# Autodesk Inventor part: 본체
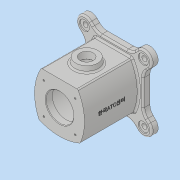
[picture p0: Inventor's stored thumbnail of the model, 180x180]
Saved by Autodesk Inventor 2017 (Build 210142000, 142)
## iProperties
Part Number: 본체
Material: 일반
Document SubType Name: Modeling
Designer: Administrator
Density: 1 g/cm^3
Appearance: 기본값
Author: Administrator
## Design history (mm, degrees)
sketch "스케치1"
  geometry: L1 (-53, 53)-(53, 53); L2 (53, 53)-(53, -53); L3 (53, -53)-(-53, -53); L4 (-53, -53)-(-53, 53); L5 (-53, 53)-(53, -53); L6 (53, 53)-(-53, -53); 1 further point
  constraints: 12 end point, 2 midpoint, 2 parallel, 1 horizontal, 1 perpendicular
  dimensions: "d0" = 106 distance of L1.end L2.end; "d1" = 106 distance of L1.start L1.end
extrude "돌출1" new body sketch "스케치1" distance "d5" = 12; taper "d6" = 0 deg
sketch "스케치2"
  geometry: L1 (53, 53)-(-53, 53) reference; L2 (0, 53)-(0, 0); L3 (-53.033, 53.033)-(0, 0); L4 (-63.64, 42.426)-(-44.143, 22.93); L5 (-42.426, 63.64)-(-22.93, 44.143); L6 (-44.143, 22.93)-(-22.93, 44.143); A1 r 15 centre (-53.033, 53.033) between (-42.426, 63.64) and (-63.64, 42.426)
  constraints: 10 end point, 2 parallel, 2 point on circle, 2 tangent, 1 centre point, 1 coincident, 1 midpoint, 1 vertical
  dimensions: "d87" = 30 diameter of A1; "d88" = 45 deg angle of L2 L3; "d89" = 75 distance of L3.start L3.end; "d90" = 21.2132 horizontal distance of L4.end L5.end; "d91" = 19.49686 horizontal distance of L5.start L5.end
extrude "돌출2" join sketch "스케치2" distance "d10" = 12; taper "d11" = 0 deg
sketch "스케치3"
  geometry: L1 (-45, 45)-(-32.942, 45); L2 (45, 45)-(45, -45); L3 (45, -45)-(-45, -45); L4 (-45, -45)-(-45, 45); L5 (-45, 45)-(45, -45); L6 (45, 45)-(-45, -45); L7 (-45, 0)-(45, 0); L8 (32.942, 45)-(45, 45); L9 (-32.942, 45)-(32.942, 45); A1 r 90 centre (0, 45) between (-45, -32.942) and (-37.029, -37.029); A2 r 90 centre (45, 0) between (-32.942, 45) and (-37.029, -37.029); A3 r 90 centre (-45, 0) between (32.942, -45) and (37.029, -37.029); A4 r 90 centre (0, 45) between (-37.029, -37.029) and (37.029, -37.029); A5 r 90 centre (45, 0) between (-37.029, -37.029) and (-32.942, -45); A6 r 90 centre (-45, 0) between (37.029, -37.029) and (32.942, 45); A7 r 90 centre (0, 45) between (37.029, -37.029) and (45, -32.942); 4 further points
  constraints: 18 end point, 18 point on circle, 7 centre point, 5 midpoint, 5 point on line, 5 tangent, 4 horizontal, 4 parallel, 3 perpendicular, 2 horizontal alignment, 1 vertical alignment
  dimensions: "d15" = 90 distance of L2.start L2.end; "d16" = 90 distance of L1.start L2.start; "d17" = 90 radius of A1; "d18" = 90 radius of A2; "d19" = 90 radius of A3; "d20" = 90 distance of L7.start L7.end
extrude "돌출3" join sketch "스케치3" distance "d21" = 98; taper "d22" = 0 deg
node "작업 평면1"
sketch "스케치4"
  geometry: L1 (31.787, 0)-(-31.787, 0) reference; C1 r 20 at (0, 61); 1 further point
  constraints: 1 centre point, 1 vertical alignment
  dimensions: "d24" = 40 diameter of C1; "d25" = 61 distance from line of L1 C1.centre
extrude "돌출4" join sketch "스케치4" stored distance "d26" = 98; taper "d27" = 10 deg
sketch "스케치5"
  geometry: C1 r 25 at (0, 0); 1 further point
  constraints: 1 centre point, 1 coincident
  dimensions: "d28" = 50 diameter of C1
extrude "돌출5" cut sketch "스케치5" distance "d29" = 12; taper "d30" = 0 deg
sketch "스케치6"
  geometry: C1 r 37 at (0, 0); 1 further point
  constraints: 1 centre point, 1 coincident
  dimensions: "d31" = 74 diameter of C1
extrude "돌출6" cut sketch "스케치6" distance "d32" = 86; taper "d33" = 0 deg
sketch "스케치7"
  geometry: C1 r 25 at (0, 0); 1 further point
  constraints: 1 centre point, 1 coincident
  dimensions: "d34" = 50 diameter of C1
extrude "돌출7" cut sketch "스케치7" stored distance "d35" = 86; taper "d36" = 0 deg
sketch "스케치8"
  geometry: C1 r 20 at (0, 0) reference; C2 r 12 at (0, 0); 1 further point
  constraints: 1 centre point, 1 coincident
  dimensions: "d37" = 24 diameter of C2
extrude "돌출8" cut sketch "스케치8" distance "d38" = 13; taper "d39" = 0 deg
sketch "스케치9"
  geometry: C1 r 12 at (0, 0) reference; C2 r 15 at (0, 0); 1 further point
  constraints: 1 centre point, 1 coincident
  dimensions: "d40" = 30 diameter of C2
extrude "돌출9" cut sketch "스케치9" stored distance "d41" = 13; taper "d42" = 0 deg
fillet "모깎기1" dims "d43" = 20
sketch "스케치10"
  geometry: L1 (0, 40)-(0, 0); L2 (0, 0)-(-28.284, 28.284); A1 r 40 centre (0, 0) between (0, 40) and (-28.284, 28.284); 2 further points
  constraints: 4 end point, 2 coincident, 2 point on circle, 1 centre point, 1 vertical
  dimensions: "d44" = 80 diameter of A1; "d45" = 45 deg angle of L1 L2
hole "구멍1" sketch "스케치10" at (-28.284, 28.284) diameter "d46" = 3.242; stored, may be unused: countersink angle "d50" = 90 deg, drill point angle "d52" = 118 deg; dims "d47" = 9, "d48" = 4, "d49" = 2, "d51" = 11
node "작업 평면2"
sketch "스케치12"
  geometry: L1 (31.787, 0)-(-31.787, 0) reference; L2 (55, 81)-(55, 41) reference; 4 further points
  constraints: 1 other
  dimensions: "d64" = 61 distance from line of L1 point (0, 61); "d65" = 55 distance from line of L2 point (0, 61)
feature "엠보싱1" sketch "스케치12" dims "d0" = 106, "d1" = 106, "d15" = 90, "d16" = 90, "d17" = 90, "d18" = 90, "d19" = 90, "d20" = 90, "d66" = 0.5, "d67" = 0
sketch "스케치13"
  geometry: L1 (40, 0)-(0, 0); L2 (0, 0)-(28.284, 28.284); C1 r 1.621 at (28.284, 28.284) reference; A1 r 40 centre (0, 0) between (40, 0) and (28.284, 28.284); 2 further points
  constraints: 4 end point, 2 coincident, 2 point on circle, 1 centre point, 1 horizontal
  dimensions: "d69" = 80 diameter of A1; "d70" = 45 deg angle of L1 L2
hole "구멍3" sketch "스케치13" at (28.284, 28.284) diameter "d71" = 3.242; stored, may be unused: countersink angle "d75" = 90 deg, drill point angle "d77" = 118 deg; dims "d72" = 9, "d73" = 18, "d74" = 2, "d76" = 11
fillet "모깎기3" dims "d81" = 3
chamfer "모따기1" distance "d82" = 1; stored, may be unused: second distance "d83" = 2, angle "d84" = 45 deg
fillet "모깎기5" dims "d92" = 3
fillet "모깎기6" dims "d93" = 3
fillet "모깎기7" dims "d94" = 3
fillet "모깎기8" dims "d95" = 3
sketch "스케치14"
  geometry: A1 r 15 centre (-53.033, 53.033) between (-42.426, 63.64) and (-63.64, 42.426) reference; A2 r 15 centre (53.033, 53.033) between (63.64, 42.426) and (42.426, 63.64) reference; A3 r 15 centre (53.033, -53.033) between (42.426, -63.64) and (63.64, -42.426) reference; A4 r 15 centre (-53.033, -53.033) between (-63.64, -42.426) and (-42.426, -63.64) reference; 5 further points
  constraints: 4 coincident
hole "구멍4" sketch "스케치14" at (-53.033, 53.033), (53.033, 53.033), (53.033, -53.033), (-53.033, -53.033) diameter "d96" = 9; stored, may be unused: countersink angle "d100" = 90 deg, drill point angle "d102" = 118 deg; dims "d97" = 9, "d98" = 18, "d99" = 2, "d101" = 11
node "솔리드1"
pattern_circular "원형 패턴1" dims angle "d13" = 360 deg
pattern_circular "원형 패턴2" dims angle "d54" = 360 deg
pattern_circular "원형 패턴3" dims angle "d79" = 360 deg
node "투영된 루프1"
other parameters: "d23" = 55, "d63" = 129.5
